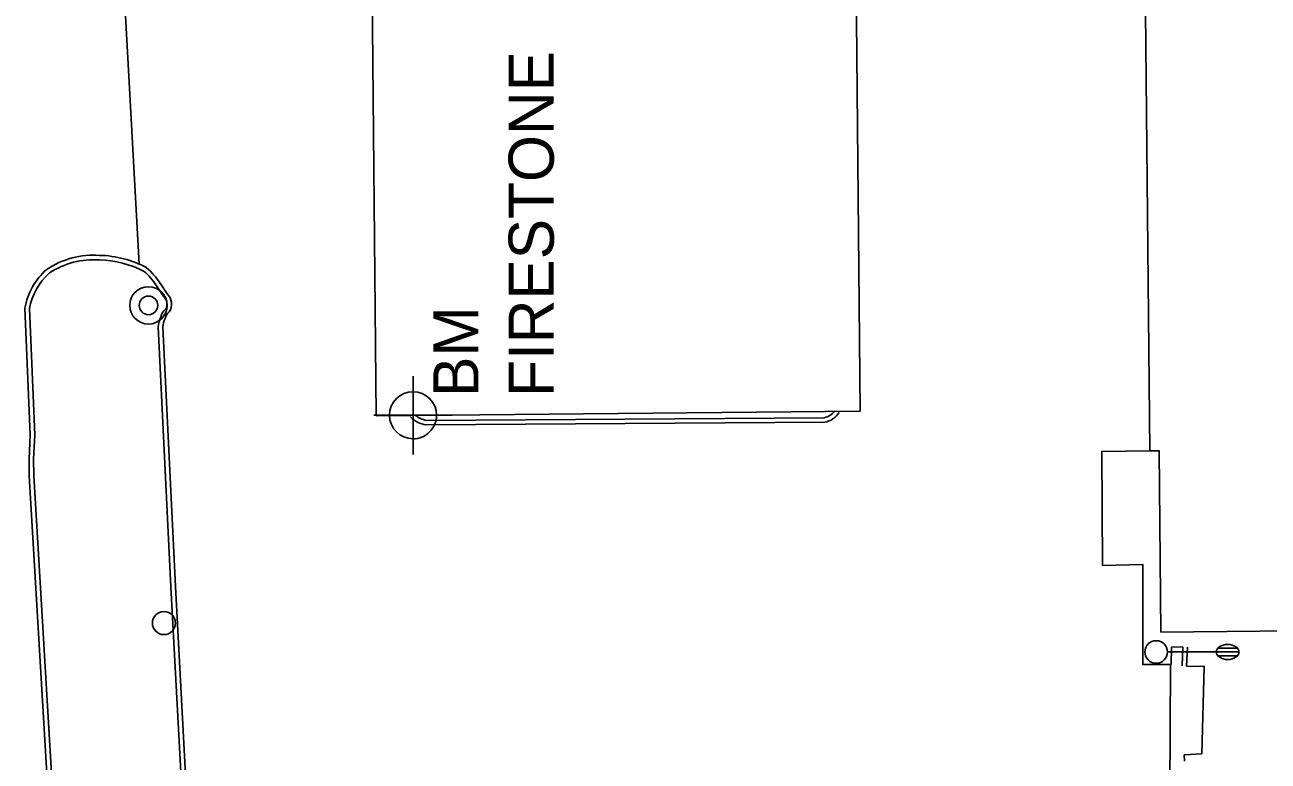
# Model space of a CAD drawing. Extents: x 2145380 to 2156929, y 139568 to 149130.
# Drawn here: x 2150960.5 to 2151125.7, y 145767 to 145864.8 of the extents above; entities that cross this region are included whole.
import ezdxf

# ---------------------------------------------------------------- set-up
doc = ezdxf.new("R2010")
doc.units = 0
for name, color, linetype in [('Default', 7, 'Continuous'), ('SURV_Benchmark', 7, 'Continuous'), ('SURV_Text', 7, 'Continuous'), ('TOPO_Asphalt', 7, 'Continuous'), ('TOPO_Building', 7, 'Continuous'), ('TOPO_Curb Back', 7, 'Continuous'), ('TOPO_Light Pole', 7, 'Continuous'), ('TOPO_San Manhole', 7, 'Continuous'), ('TOPO_Water Meter', 7, 'Continuous')]:
    doc.layers.add(name, color=color, linetype=linetype)

# ---------------------------------------------------------------- blocks, each defined once
blk = doc.blocks.new('LP')
at = {"layer": 'TOPO_Light Pole'}
blk.add_line((3.81, 0), (20.32, 0), dxfattribs=at)
for points in [[(20.32, 0), (27.94, 0)], [(20.32, 0), (23.5, 0)], [(20.83, 1.27), (27.43, 1.27)], [(20.83, 1.27), (23.5, 1.27)], [(23.71, 1.27), (27.43, 1.27)], [(23.71, 0), (27.94, 0)], [(20.83, -1.27), (27.43, -1.27)], [(20.83, -1.27), (23.5, -1.27)], [(23.71, -1.27), (27.43, -1.27)]]:
    blk.add_lwpolyline(points, dxfattribs=at)
blk.add_circle((0, 0), 3.81, dxfattribs=at)
blk.add_ellipse((24.13, 0), major_axis=(3.81, 0), ratio=0.666667, dxfattribs=at)
blk = doc.blocks.new('WTRMTR')
at = {"layer": 'Default'}
blk.add_circle((0, 0), 3.89, dxfattribs=at)
blk = doc.blocks.new('EXMHSS')
at = {"layer": 'Default'}
for radius in [6.3, 3.13]:
    blk.add_circle((0, 0), radius, dxfattribs=at)
blk = doc.blocks.new('BM')
at = {"layer": 'SURV_Benchmark'}
for p, q in [((0, 2.49), (0, 4.15)), ((-2.49, 0), (-4.16, 0)), ((4.16, 0), (2.49, 0)), ((0, -4.16), (0, -2.49))]:
    blk.add_line(p, q, dxfattribs=at)
for points in [[(0, 2.49), (0, 2.49), (0, 0), (2.49, 0), (2.49, 0), (2.49, 0)], [(0, 2.49), (0, 2.49), (0, 0), (2.49, 0), (2.49, 0), (2.49, 0), (2.49, 0)], [(-2.5, 0), (-2.49, 0), (0, 0), (0, -2.49), (0, -2.49)], [(-2.5, 0), (-2.49, 0), (0, 0), (0, -2.49), (0, -2.49)]]:
    blk.add_lwpolyline(points, dxfattribs=at)
for start, end in [(90.0638, 180.0068), (0.0638, 90.0068), (0.0638, 90.0068), (180.0638, 270.0068), (180.0638, 270.0068), (269.9472, 359.9927)]:
    blk.add_arc((0, 0), 2.5, start, end, dxfattribs=at)

msp = doc.modelspace()

# ---------------------------------------------------------------- linework, layer by layer
at = {"layer": 'TOPO_Asphalt'}
for points in [[(2150971.18, 145874.16), (2150973.51, 145873.27), (2150975.75, 145833.01)], [(2151114.39, 145782.17), (2151112.86, 145782.13), (2151112.81, 145779.85), (2151109.07, 145779.84), (2151109.07, 145793.12), (2151103.72, 145793.01), (2151103.61, 145808.13), (2151109.97, 145808.22)], [(2151024.44, 145718.43), (2151063.85, 145720.14), (2151064.05, 145715.1), (2151068.01, 145715.14), (2151067.85, 145720.06), (2151112.44, 145720.94), (2151112.74, 145779.85)], [(2151114.88, 145779.62), (2151117.21, 145779.6), (2151116.89, 145767.99), (2151114.57, 145767.84), (2151114.58, 145767.02)]]:
    msp.add_lwpolyline(points, dxfattribs=at)
at = {"layer": 'TOPO_Building'}
msp.add_lwpolyline([(2151171.94, 145881.01), (2151172.88, 145784.76), (2151111.47, 145784.16), (2151111.23, 145808.23), (2151109.97, 145808.22), (2151109.28, 145880.07), (2151070.88, 145879.7), (2151071.52, 145813.5), (2151007.23, 145812.88), (2151006.64, 145873.96), (2150993.06, 145873.83), (2150992.7, 145910.67), (2151014.52, 145910.88), (2151014.53, 145909.77), (2151156.7, 145911.15), (2151156.99, 145880.87)], close=True, dxfattribs=at)
at = {"layer": 'TOPO_Curb Back'}
for p, q in [((2151114.28, 145779.65), (2151114.39, 145782.17)), ((2151114.88, 145779.62), (2151114.99, 145782.14))]:
    msp.add_line(p, q, dxfattribs=at)
for points in [[(2150978.02, 145830.14), (2150978.99, 145828.68)], [(2150978.53, 145830.46), (2150979.46, 145829.07)], [(2150966.18, 145724.65), (2150964.77, 145743.68), (2150961.13, 145804.91), (2150961.1, 145807.1), (2150961.27, 145810.35), (2150960.55, 145827.14)], [(2150966.78, 145724.72), (2150965.37, 145743.72), (2150961.73, 145804.93), (2150961.7, 145807.09), (2150961.87, 145810.35), (2150961.15, 145827.1)], [(2150978.27, 145824.68), (2150979.94, 145790.17), (2150982.86, 145736.02), (2150983.72, 145717.39), (2151002.33, 145717.91), (2151022.79, 145718.09)], [(2150978.87, 145824.66), (2150980.54, 145790.2), (2150983.46, 145736.05), (2150984.3, 145718.01), (2151002.32, 145718.51), (2151022.78, 145718.69)], [(2151013.82, 145811.66), (2151066.8, 145812.01)], [(2151013.88, 145812.26), (2151066.74, 145812.61)]]:
    msp.add_lwpolyline(points, dxfattribs=at)
for centre, radius, start, end in [((2150969.67, 145823.06), 11.14, 85.8136, 123.8896), ((2150969.67, 145823.06), 10.54, 85.7339, 123.6839), ((2150970.14, 145820.11), 13.46, 62.3638, 88.6896), ((2150970.14, 145820.12), 14.06, 62.0875, 88.6274), ((2150969.26, 145825.65), 8.83, 131.0588, 170.277), ((2150969.26, 145825.65), 8.23, 131.3196, 169.839), ((2150970.98, 145825.74), 8.3, 32.0203, 49.4071), ((2150970.98, 145825.73), 8.9, 32.0803, 49.8437), ((2150978.02, 145827.68), 1.4, 333.4983, 46.1429), ((2150978.02, 145827.68), 2, 329.1792, 44.1131), ((2150980.51, 145825.55), 1.95, 129.4798, 167.4583), ((2150983.61, 145823.94), 5.4, 157.9325, 172.0912), ((2150983.61, 145823.94), 4.8, 157.2992, 171.4405), ((2150980.51, 145825.55), 1.35, 125.0323, 169.4461), ((2151014.49, 145815.49), 3.88, 225.7389, 260.1937), ((2151014.49, 145815.49), 3.28, 231.2791, 259.3018), ((2151066.28, 145814.85), 2.28, 281.5556, 322.7725), ((2151066.28, 145814.85), 2.88, 280.3235, 327.7705)]:
    msp.add_arc(centre, radius, start, end, dxfattribs=at)

# ---------------------------------------------------------------- block references
at = {"layer": 'SURV_Benchmark', "xscale": 1.25, "yscale": 1.25}
msp.add_blockref('BM', (2151012.11, 145812.94), dxfattribs=at)
at = {"layer": 'TOPO_Light Pole', "xscale": 0.39370000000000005, "yscale": 0.3937000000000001}
msp.add_blockref('LP', (2151110.83, 145781.51), dxfattribs=at)
at = {"layer": 'TOPO_San Manhole', "xscale": 0.39370000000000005, "yscale": 0.3937000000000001}
msp.add_blockref('EXMHSS', (2150976.97, 145827.53), dxfattribs=at)
at = {"layer": 'TOPO_Water Meter', "xscale": 0.39370000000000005, "yscale": 0.3937000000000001}
msp.add_blockref('WTRMTR', (2150979.02, 145785.35), dxfattribs=at)

# ---------------------------------------------------------------- texts
at = {"layer": 'SURV_Text'}
for s, p in [('FIRESTONE', (2151030.81, 145815.38)), ('BM', (2151020.81, 145815.38))]:
    msp.add_text(s, height=6, rotation=90, dxfattribs=at).set_placement(p)

doc.saveas('drawing.dxf')
